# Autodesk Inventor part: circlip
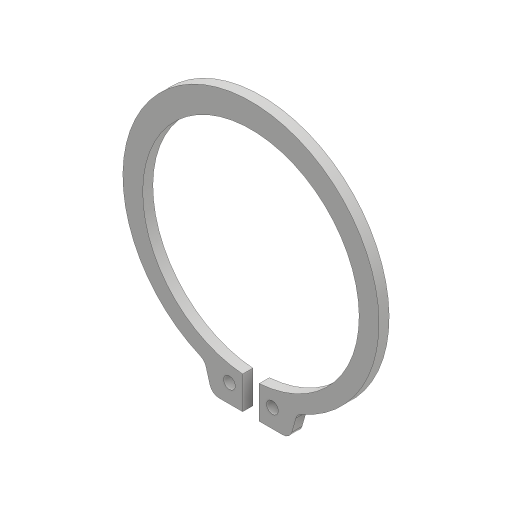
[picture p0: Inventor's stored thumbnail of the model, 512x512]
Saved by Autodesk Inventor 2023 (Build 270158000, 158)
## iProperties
Created: 2016-06
Part Number: circlip
Material: Generic
Document SubType Name: Modeling
Designer: CADCIM
Density: 1 g/cm^3
Appearance: Default
Author: CADCIM
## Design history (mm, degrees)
sketch "Sketch1"
  geometry: L1 (9.52, -25.305)-(8.665, -28.284); L2 (6.743, -29.733)-(1.75, -29.733); L3 (1.75, -29.733)-(1.75, -22.833); L4 (0, 0)-(0, -33.55); L5 (-6.743, -29.733)-(-1.75, -29.733); L6 (-1.75, -29.733)-(-1.75, -22.833); L7 (-9.52, -25.305)-(-8.665, -28.284); C1 r 1.25 at (4.55, -25.815); C2 r 1.25 at (-4.55, -25.815); A1 r 22.9 centre (0, 0) between (1.75, -22.833) and (-1.75, -22.833); A2 r 27.1 centre (0, 0.9) between (10.656, -24.017) and (-10.656, -24.017); A3 r 2 centre (-6.743, -27.733) between (-8.665, -28.284) and (-6.743, -29.733); A4 r 2 centre (-11.442, -25.856) between (-9.52, -25.305) and (-10.656, -24.017); A5 r 2 centre (11.442, -25.856) between (10.656, -24.017) and (9.52, -25.305); A6 r 2 centre (6.743, -27.733) between (6.743, -29.733) and (8.665, -28.284); 12 further points
  constraints: 18 point on circle, 14 end point, 8 centre point, 8 point on line, 8 tangent, 4 equal radius, 4 symmetric about line, 2 coincident, 2 midpoint, 1 horizontal, 1 horizontal alignment, 1 perpendicular, 1 vertical
  dimensions: "d0" = 45.8 diameter of A1; "d4" = 6.9 distance from line of L6.end L5; "d5" = 5.1 distance of point (0, 28) point (0, 22.9); "d6" = 2.5 diameter of C1; "d8" = 2 radius of A3 (derived); "d9" = 2.8 distance from line of C1.centre L3; "d10" = 3.5 distance of L5.end L2.end; "d11" = 27.1 radius of A2; "d14" = 6.5 distance of L5.end point (-8.25, -29.733); "d15" = 32 deg angle of L7 L1
extrude "Extrusion1" new body sketch "Sketch1" distance "d16" = 2.15; taper "d17" = 0 deg
body "Solid1"
other parameters: "d18" = 0
